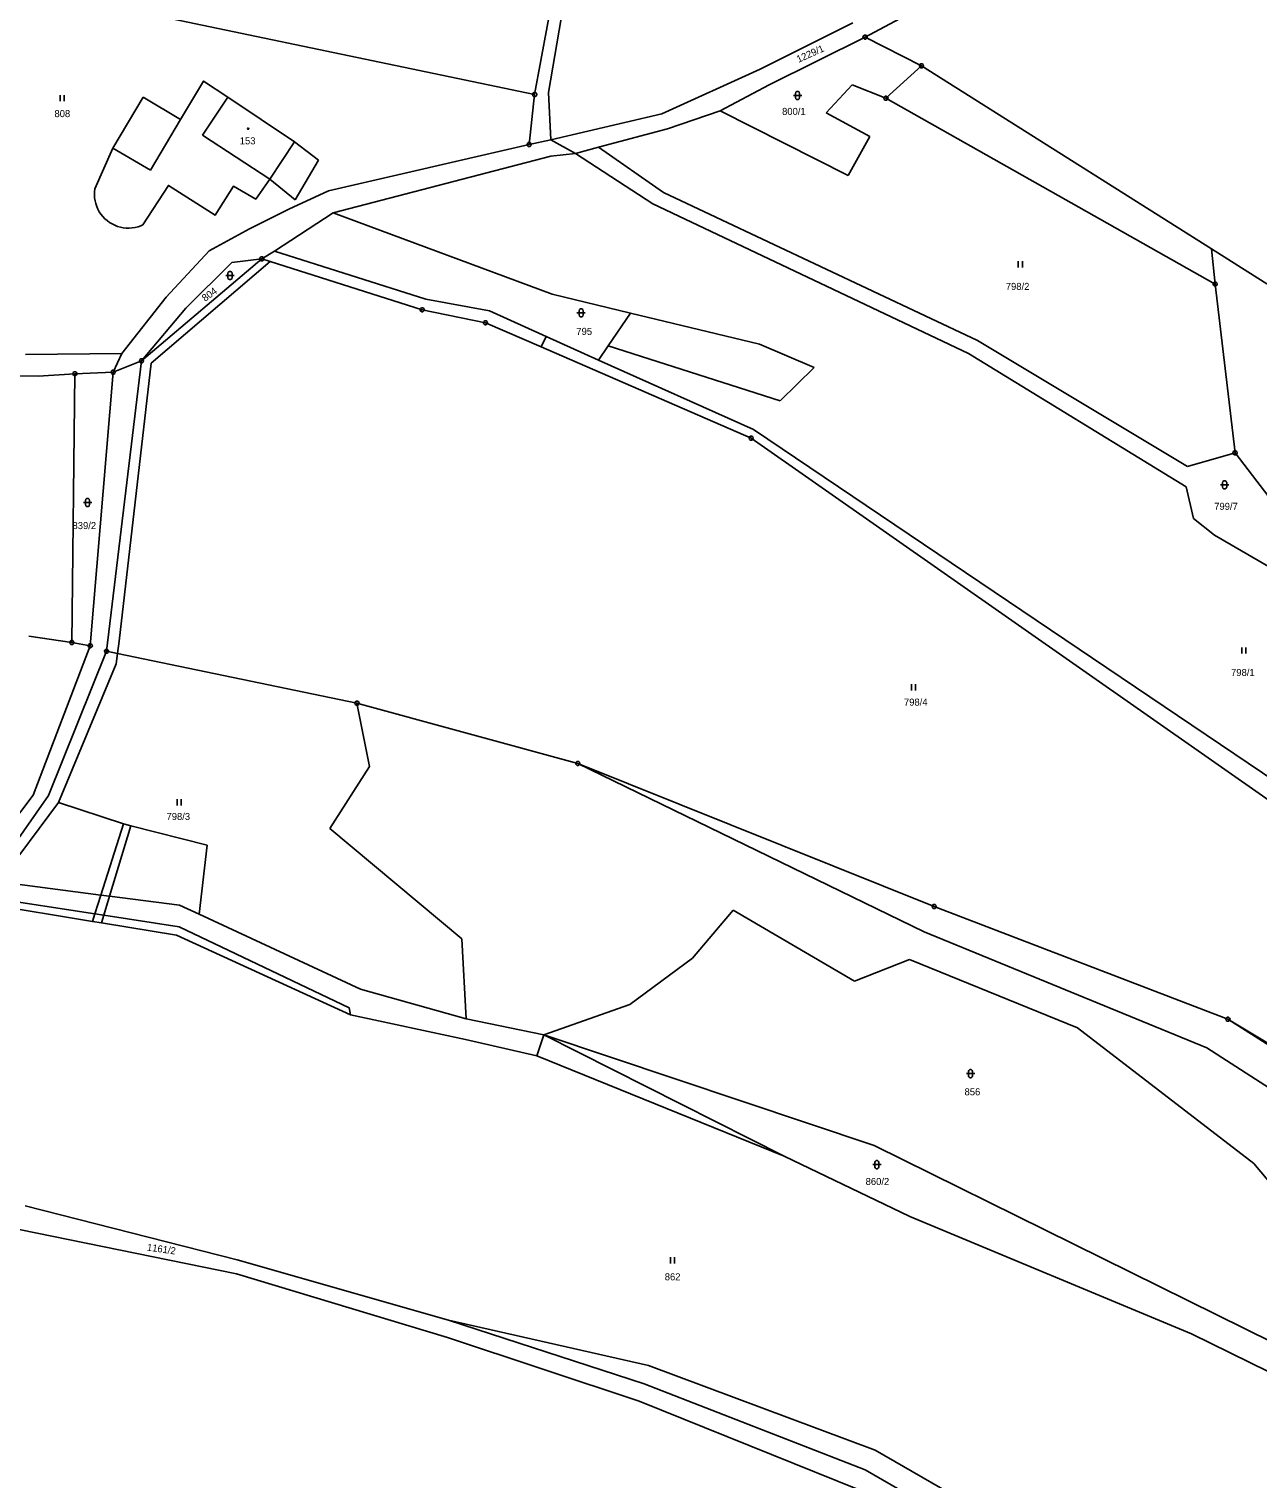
# Model space of a CAD drawing. Extents: x -694465 to -690527, y -983694 to -978978.
# Drawn here: x -691076.6 to -690780.2, y -981049.8 to -980700.1 of the extents above; entities that cross this region are included whole.
import ezdxf

# ---------------------------------------------------------------- set-up
doc = ezdxf.new("R2010")
doc.units = 0
for name, color, linetype in [('Vrstva 1', 7, 'Continuous'), ('Vrstva 18', 7, 'Continuous'), ('Vrstva 19', 7, 'Continuous'), ('Vrstva 24', 7, 'Continuous'), ('Vrstva 25', 7, 'Continuous')]:
    doc.layers.add(name, color=color, linetype=linetype)

msp = doc.modelspace()

# ---------------------------------------------------------------- linework, layer by layer
at = {"layer": 'Vrstva 1'}
for p, q in [((-690944.8, -980730.07), (-690950.76, -980726.8)), ((-690931.555, -980768.6), (-690950.4, -980764.07)), ((-690931.555, -980768.6), (-690936.87, -980776.46)), ((-690931.555, -980768.6), (-690900.39, -980776.09))]:
    msp.add_line(p, q, dxfattribs=at)
for points in [[(-690945.48, -980666.56), (-690954.63, -980715.88)], [(-690951.26, -980715.36), (-690943.69, -980670.66)], [(-690874.96, -980702.01), (-690852.18, -980689.8)], [(-691075.66, -980690.57), (-690954.63, -980715.88)], [(-690877.88, -980698.61), (-690900.24, -980709.79)], [(-690874.96, -980702.01), (-690898.05, -980713.5)], [(-690861.36, -980708.96), (-690874.96, -980702.01)], [(-690900.24, -980709.79), (-690923.97, -980720.55)], [(-690869.93, -980716.78), (-690861.36, -980708.96)], [(-690791.426, -980753.137), (-690861.36, -980708.96)], [(-691040, -980721.87), (-691034.47, -980712.65), (-691028.62, -980716.55)], [(-690898.05, -980713.5), (-690909.88, -980719.84)], [(-690884.37, -980720.29), (-690878.05, -980713.57)], [(-690878.05, -980713.57), (-690869.93, -980716.78)], [(-691056.31, -980728.8), (-691049.06, -980716.52)], [(-691049.06, -980716.52), (-691040, -980721.87)], [(-691034.73, -980725.67), (-691028.62, -980716.55)], [(-691028.62, -980716.55), (-691012.51, -980727.29)], [(-690954.63, -980715.88), (-690955.97, -980727.94)], [(-690950.76, -980726.8), (-690951.26, -980715.36)], [(-690869.93, -980716.78), (-690790.56, -980761.6)], [(-690923.97, -980720.55), (-690950.76, -980726.8)], [(-690922.57, -980724.17), (-690909.88, -980719.84)], [(-690909.88, -980719.84), (-690879.03, -980735.39)], [(-690873.8, -980726.01), (-690884.37, -980720.29)], [(-691040, -980721.87), (-691047.26, -980734.15)], [(-690939.26, -980728.61), (-690922.57, -980724.17)], [(-691018.45, -980736.26), (-691034.73, -980725.67)], [(-691012.51, -980727.29), (-691018.45, -980736.26)], [(-691012.51, -980727.29), (-691006.72, -980731.75)], [(-690955.97, -980727.94), (-691004.33, -980739.14)], [(-690955.97, -980727.94), (-690950.76, -980726.8)], [(-690879.03, -980735.39), (-690873.8, -980726.01)], [(-691018.45, -980736.26), (-691021.87, -980741.09), (-691027.27, -980737.99), (-691031.68, -980744.98), (-691042.95, -980737.81), (-691049.14, -980747.34), (-691049.59, -980747.53), (-691050.27, -980747.77), (-691050.97, -980747.94), (-691051.68, -980748.05), (-691052.39, -980748.1), (-691053.11, -980748.08), (-691053.82, -980748.01), (-691054.52, -980747.87), (-691055.21, -980747.67), (-691055.88, -980747.41), (-691056.52, -980747.09), (-691057.14, -980746.72), (-691057.72, -980746.3), (-691058.26, -980745.83), (-691058.75, -980745.31), (-691059.2, -980744.75), (-691059.6, -980744.16), (-691059.95, -980743.53), (-691060.24, -980742.88), (-691060.47, -980742.2), (-691060.64, -980741.5), (-691060.75, -980740.79), (-691060.8, -980740.08), (-691060.79, -980739.36), (-691060.71, -980738.65), (-691056.31, -980728.8)], [(-691047.26, -980734.15), (-691056.31, -980728.8)], [(-691006.72, -980731.75), (-691012.35, -980741.28)], [(-691003.19, -980744.43), (-690950.72, -980730.72)], [(-690950.72, -980730.72), (-690944.8, -980730.07)], [(-690939.26, -980728.61), (-690944.8, -980730.07)], [(-690944.8, -980730.07), (-690926.14, -980742.28)], [(-690923.55, -980739.51), (-690939.26, -980728.61)], [(-691012.35, -980741.28), (-691018.45, -980736.26)], [(-691004.33, -980739.14), (-691013.9, -980743.51)], [(-690926.14, -980742.28), (-690850.03, -980778.35)], [(-690847.83, -980775.17), (-690923.55, -980739.51)], [(-691013.9, -980743.51), (-691023.4, -980748.27)], [(-691003.19, -980744.43), (-691017.38, -980753.7)], [(-690950.4, -980764.07), (-691003.19, -980744.43)], [(-691023.4, -980748.27), (-691033.14, -980753.6)], [(-691049.45, -980780.12), (-691020.44, -980755.51)], [(-691018.379, -980756.164), (-691047.13, -980780.646)], [(-691033.14, -980753.6), (-691043.51, -980764.76)], [(-691020.44, -980755.51), (-691027.65, -980756.38)], [(-691017.38, -980753.7), (-691020.44, -980755.51)], [(-691020.44, -980755.51), (-691018.379, -980756.164)], [(-691018.379, -980756.164), (-690981.72, -980767.79)], [(-690980.89, -980765.24), (-691017.38, -980753.7)], [(-690764.51, -980770.14), (-690791.426, -980753.137)], [(-690790.56, -980761.6), (-690791.426, -980753.137)], [(-691027.65, -980756.38), (-691038.74, -980767.37)], [(-690790.56, -980761.6), (-690785.76, -980802.28)], [(-691043.51, -980764.76), (-691054.14, -980778.31)], [(-690965.48, -980768.06), (-690980.89, -980765.24)], [(-691038.74, -980767.37), (-691049.45, -980780.12)], [(-690981.72, -980767.79), (-690966.48, -980770.92)], [(-690951.838, -980774.239), (-690965.48, -980768.06)], [(-690966.48, -980770.92), (-690953.088, -980776.742)], [(-690951.838, -980774.239), (-690953.088, -980776.742)], [(-690953.088, -980776.742), (-690902.42, -980798.77)], [(-690939.23, -980779.95), (-690951.838, -980774.239)], [(-690939.23, -980779.95), (-690936.87, -980776.46)], [(-690936.87, -980776.46), (-690895.43, -980789.74)], [(-690887.26, -980781.76), (-690900.39, -980776.09)], [(-690797.24, -980805.59), (-690847.83, -980775.17)], [(-691054.14, -980778.31), (-691077.42, -980778.6)], [(-691057.87, -980850.16), (-691049.45, -980780.12)], [(-691056.28, -980782.84), (-691054.14, -980778.31)], [(-691049.45, -980780.12), (-691056.28, -980782.84)], [(-691047.13, -980780.646), (-691054.784, -980847.69)], [(-690901.83, -980796.7), (-690939.23, -980779.95)], [(-690850.03, -980778.35), (-690797.54, -980810.54)], [(-691105.24, -980783.63), (-691074.36, -980783.83)], [(-691074.36, -980783.83), (-691065.48, -980783.21)], [(-691065.48, -980783.21), (-691066.25, -980848.06)], [(-691065.48, -980783.21), (-691056.28, -980782.84)], [(-691056.28, -980782.84), (-691061.78, -980848.83)], [(-690895.43, -980789.74), (-690887.26, -980781.76)], [(-690775.67, -980881.81), (-690901.83, -980796.7)], [(-690902.42, -980798.77), (-690775.89, -980887.32)], [(-690785.76, -980802.28), (-690797.24, -980805.59)], [(-690764.26, -980830.36), (-690785.76, -980802.28)], [(-690797.54, -980810.54), (-690795.79, -980818.16)], [(-690795.79, -980818.16), (-690790.72, -980822.14)], [(-690790.72, -980822.14), (-690771.18, -980833.48)], [(-691066.25, -980848.06), (-691076.63, -980846.5)], [(-691061.78, -980848.83), (-691075.56, -980884.9)], [(-691071.88, -980884.94), (-691057.87, -980850.16)], [(-691066.25, -980848.06), (-691061.78, -980848.83)], [(-691055.208, -980850.712), (-691057.87, -980850.16)], [(-691055.208, -980850.712), (-691055.557, -980853.196)], [(-691054.784, -980847.69), (-691055.208, -980850.712)], [(-690997.47, -980862.69), (-691055.208, -980850.712)], [(-691055.557, -980853.196), (-691069.466, -980886.636)], [(-690944.22, -980877.22), (-690997.47, -980862.69)], [(-690997.47, -980862.69), (-690994.46, -980878)], [(-690994.46, -980878), (-691003.99, -980892.92)], [(-690858.32, -980911.72), (-690944.22, -980877.22)], [(-690944.22, -980877.22), (-690860.72, -980917.85)], [(-691075.56, -980884.9), (-691090.27, -980904.24)], [(-691086.28, -980905.49), (-691071.88, -980884.94)], [(-691069.466, -980886.636), (-691083.772, -980905.811)], [(-691069.466, -980886.636), (-691053.772, -980891.769)], [(-691053.772, -980891.769), (-691059.211, -980908.956)], [(-691051.963, -980892.235), (-691057.142, -980909.221)], [(-691053.772, -980891.769), (-691051.963, -980892.235)], [(-691051.963, -980892.235), (-691033.627, -980896.958)], [(-691003.99, -980892.92), (-690972.23, -980919.52)], [(-691033.627, -980896.958), (-691035.534, -980913.581)], [(-691059.211, -980908.956), (-691083.772, -980905.811)], [(-691060.648, -980913.494), (-691085.903, -980909.628)], [(-691059.211, -980908.956), (-691060.648, -980913.494)], [(-691057.142, -980909.221), (-691059.211, -980908.956)], [(-691057.142, -980909.221), (-691058.543, -980913.816)], [(-691040.28, -980911.38), (-691057.142, -980909.221)], [(-691086.455, -980911.146), (-691061.223, -980915.312)], [(-691060.648, -980913.494), (-691061.223, -980915.312)], [(-691058.543, -980913.816), (-691060.648, -980913.494)], [(-691035.534, -980913.581), (-691040.28, -980911.38)], [(-690996.61, -980931.63), (-691035.534, -980913.581)], [(-690906.8, -980912.6), (-690916.54, -980924.16)], [(-690877.49, -980929.73), (-690906.8, -980912.6)], [(-690787.46, -980938.93), (-690858.32, -980911.72)], [(-691061.223, -980915.312), (-691059.106, -980915.662)], [(-691058.543, -980913.816), (-691059.106, -980915.662)], [(-691059.106, -980915.662), (-691041.01, -980918.65)], [(-691040.353, -980916.601), (-691058.543, -980913.816)], [(-691040.353, -980916.601), (-690999.318, -980936.185), (-690999, -980937.84)], [(-691041.01, -980918.65), (-690999, -980937.84)], [(-690972.23, -980919.52), (-690971.18, -980938.81)], [(-690860.72, -980917.85), (-690792.58, -980945.83)], [(-690916.54, -980924.16), (-690931.71, -980935.34)], [(-690864.23, -980924.53), (-690877.49, -980929.73)], [(-690823.72, -980940.99), (-690864.23, -980924.53)], [(-690971.18, -980938.81), (-690996.61, -980931.63)], [(-690999, -980937.84), (-690971.32, -980943.84)], [(-690931.71, -980935.34), (-690952.43, -980942.7)], [(-690952.43, -980942.7), (-690971.18, -980938.81)], [(-690781.23, -980973.71), (-690823.72, -980940.99)], [(-690643.63, -981025.36), (-690787.46, -980938.93)], [(-690636.2, -981034.92), (-690787.46, -980938.93)], [(-690971.32, -980943.84), (-690954.09, -980947.72)], [(-690954.09, -980947.72), (-690952.43, -980942.7)], [(-690952.43, -980942.7), (-690894.47, -980971.92)], [(-690872.79, -980969.37), (-690952.43, -980942.7)], [(-690894.47, -980971.92), (-690954.09, -980947.72)], [(-690792.58, -980945.83), (-690743.36, -980977.51)], [(-690776.49, -981016.99), (-690872.79, -980969.37)], [(-690894.47, -980971.92), (-690864.17, -980986.51)], [(-690758.75, -981000.52), (-690781.23, -980973.71)], [(-691026.38, -980996.99), (-691077.45, -980983.96)], [(-690864.17, -980986.51), (-690796.27, -981014.8)], [(-691078.96, -980989.62), (-691026.49, -981000.36)], [(-690975.39, -981011.49), (-691026.38, -980996.99)], [(-691026.49, -981000.36), (-690975.65, -981015.66)], [(-690927.18, -981022.44), (-690975.39, -981011.49)], [(-690975.39, -981011.49), (-690928.23, -981026.86)], [(-690796.27, -981014.8), (-690731.16, -981046.82)], [(-690975.65, -981015.66), (-690929.44, -981031.04)], [(-690872.49, -981042.88), (-690927.18, -981022.44)], [(-690928.23, -981026.86), (-690874.9, -981047.64)], [(-690929.44, -981031.04), (-690876.42, -981052.46)], [(-690787.89, -981091.69), (-690872.49, -981042.88)], [(-690874.9, -981047.64), (-690791.5, -981095.75)]]:
    msp.add_lwpolyline(points, dxfattribs=at)
at = {"layer": 'Vrstva 24'}
for points in [[(-690874.806, -980701.534), (-690874.556, -980701.716), (-690874.46, -980702.01), (-690874.556, -980702.304), (-690874.806, -980702.486), (-690875.114, -980702.486), (-690875.364, -980702.304), (-690875.46, -980702.01), (-690875.364, -980701.716), (-690875.114, -980701.534)], [(-690861.206, -980708.484), (-690860.956, -980708.666), (-690860.86, -980708.96), (-690860.956, -980709.254), (-690861.206, -980709.436), (-690861.514, -980709.436), (-690861.764, -980709.254), (-690861.86, -980708.96), (-690861.764, -980708.666), (-690861.514, -980708.484)], [(-690954.476, -980715.404), (-690954.226, -980715.586), (-690954.13, -980715.88), (-690954.226, -980716.174), (-690954.476, -980716.356), (-690954.784, -980716.356), (-690955.034, -980716.174), (-690955.13, -980715.88), (-690955.034, -980715.586), (-690954.784, -980715.404)], [(-690869.776, -980716.304), (-690869.526, -980716.486), (-690869.43, -980716.78), (-690869.526, -980717.074), (-690869.776, -980717.256), (-690870.084, -980717.256), (-690870.334, -980717.074), (-690870.43, -980716.78), (-690870.334, -980716.486), (-690870.084, -980716.304)], [(-690955.816, -980727.464), (-690955.566, -980727.646), (-690955.47, -980727.94), (-690955.566, -980728.234), (-690955.816, -980728.416), (-690956.124, -980728.416), (-690956.374, -980728.234), (-690956.47, -980727.94), (-690956.374, -980727.646), (-690956.124, -980727.464)], [(-691020.286, -980755.034), (-691020.036, -980755.216), (-691019.94, -980755.51), (-691020.036, -980755.804), (-691020.286, -980755.986), (-691020.594, -980755.986), (-691020.844, -980755.804), (-691020.94, -980755.51), (-691020.844, -980755.216), (-691020.594, -980755.034)], [(-690790.406, -980761.124), (-690790.156, -980761.306), (-690790.06, -980761.6), (-690790.156, -980761.894), (-690790.406, -980762.076), (-690790.714, -980762.076), (-690790.964, -980761.894), (-690791.06, -980761.6), (-690790.964, -980761.306), (-690790.714, -980761.124)], [(-690981.566, -980767.314), (-690981.316, -980767.496), (-690981.22, -980767.79), (-690981.316, -980768.084), (-690981.566, -980768.266), (-690981.874, -980768.266), (-690982.124, -980768.084), (-690982.22, -980767.79), (-690982.124, -980767.496), (-690981.874, -980767.314)], [(-690966.326, -980770.444), (-690966.076, -980770.626), (-690965.98, -980770.92), (-690966.076, -980771.214), (-690966.326, -980771.396), (-690966.634, -980771.396), (-690966.884, -980771.214), (-690966.98, -980770.92), (-690966.884, -980770.626), (-690966.634, -980770.444)], [(-691049.296, -980779.644), (-691049.046, -980779.826), (-691048.95, -980780.12), (-691049.046, -980780.414), (-691049.296, -980780.596), (-691049.604, -980780.596), (-691049.854, -980780.414), (-691049.95, -980780.12), (-691049.854, -980779.826), (-691049.604, -980779.644)], [(-691065.326, -980782.734), (-691065.076, -980782.916), (-691064.98, -980783.21), (-691065.076, -980783.504), (-691065.326, -980783.686), (-691065.634, -980783.686), (-691065.884, -980783.504), (-691065.98, -980783.21), (-691065.884, -980782.916), (-691065.634, -980782.734)], [(-691056.126, -980782.364), (-691055.876, -980782.546), (-691055.78, -980782.84), (-691055.876, -980783.134), (-691056.126, -980783.316), (-691056.434, -980783.316), (-691056.684, -980783.134), (-691056.78, -980782.84), (-691056.684, -980782.546), (-691056.434, -980782.364)], [(-690902.266, -980798.294), (-690902.016, -980798.476), (-690901.92, -980798.77), (-690902.016, -980799.064), (-690902.266, -980799.246), (-690902.574, -980799.246), (-690902.824, -980799.064), (-690902.92, -980798.77), (-690902.824, -980798.476), (-690902.574, -980798.294)], [(-690785.606, -980801.804), (-690785.356, -980801.986), (-690785.26, -980802.28), (-690785.356, -980802.574), (-690785.606, -980802.756), (-690785.914, -980802.756), (-690786.164, -980802.574), (-690786.26, -980802.28), (-690786.164, -980801.986), (-690785.914, -980801.804)], [(-691066.096, -980847.584), (-691065.846, -980847.766), (-691065.75, -980848.06), (-691065.846, -980848.354), (-691066.096, -980848.536), (-691066.404, -980848.536), (-691066.654, -980848.354), (-691066.75, -980848.06), (-691066.654, -980847.766), (-691066.404, -980847.584)], [(-691061.626, -980848.354), (-691061.376, -980848.536), (-691061.28, -980848.83), (-691061.376, -980849.124), (-691061.626, -980849.306), (-691061.934, -980849.306), (-691062.184, -980849.124), (-691062.28, -980848.83), (-691062.184, -980848.536), (-691061.934, -980848.354)], [(-691057.716, -980849.684), (-691057.466, -980849.866), (-691057.37, -980850.16), (-691057.466, -980850.454), (-691057.716, -980850.636), (-691058.024, -980850.636), (-691058.274, -980850.454), (-691058.37, -980850.16), (-691058.274, -980849.866), (-691058.024, -980849.684)], [(-690997.316, -980862.214), (-690997.066, -980862.396), (-690996.97, -980862.69), (-690997.066, -980862.984), (-690997.316, -980863.166), (-690997.624, -980863.166), (-690997.874, -980862.984), (-690997.97, -980862.69), (-690997.874, -980862.396), (-690997.624, -980862.214)], [(-690944.066, -980876.744), (-690943.816, -980876.926), (-690943.72, -980877.22), (-690943.816, -980877.514), (-690944.066, -980877.696), (-690944.374, -980877.696), (-690944.624, -980877.514), (-690944.72, -980877.22), (-690944.624, -980876.926), (-690944.374, -980876.744)], [(-690858.166, -980911.244), (-690857.916, -980911.426), (-690857.82, -980911.72), (-690857.916, -980912.014), (-690858.166, -980912.196), (-690858.474, -980912.196), (-690858.724, -980912.014), (-690858.82, -980911.72), (-690858.724, -980911.426), (-690858.474, -980911.244)], [(-690787.306, -980938.454), (-690787.056, -980938.636), (-690786.96, -980938.93), (-690787.056, -980939.224), (-690787.306, -980939.406), (-690787.614, -980939.406), (-690787.864, -980939.224), (-690787.96, -980938.93), (-690787.864, -980938.636), (-690787.614, -980938.454)]]:
    msp.add_lwpolyline(points, close=True, dxfattribs=at)
for points in [[(-690875.079, -980702.01), (-690874.84, -980702.01)], [(-690861.479, -980708.96), (-690861.24, -980708.96)], [(-690954.749, -980715.88), (-690954.51, -980715.88)], [(-690870.049, -980716.78), (-690869.81, -980716.78)], [(-690956.089, -980727.94), (-690955.85, -980727.94)], [(-691020.559, -980755.51), (-691020.32, -980755.51)], [(-690790.679, -980761.6), (-690790.44, -980761.6)], [(-690981.839, -980767.79), (-690981.6, -980767.79)], [(-690966.599, -980770.92), (-690966.36, -980770.92)], [(-691049.569, -980780.12), (-691049.33, -980780.12)], [(-691065.599, -980783.21), (-691065.36, -980783.21)], [(-691056.399, -980782.84), (-691056.16, -980782.84)], [(-690902.539, -980798.77), (-690902.3, -980798.77)], [(-690785.879, -980802.28), (-690785.64, -980802.28)], [(-691066.369, -980848.06), (-691066.13, -980848.06)], [(-691061.899, -980848.83), (-691061.66, -980848.83)], [(-691057.989, -980850.16), (-691057.75, -980850.16)], [(-690997.589, -980862.69), (-690997.35, -980862.69)], [(-690944.339, -980877.22), (-690944.1, -980877.22)], [(-690858.439, -980911.72), (-690858.2, -980911.72)], [(-690787.579, -980938.93), (-690787.34, -980938.93)]]:
    msp.add_lwpolyline(points, dxfattribs=at)
at = {"layer": 'Vrstva 25'}
for points in [[(-691069.04, -980716), (-691069.04, -980717.5)], [(-691068.04, -980717.5), (-691068.04, -980716)], [(-690892.24, -980716.1), (-690890.24, -980716.1)], [(-690838.03, -980756.11), (-690838.03, -980757.61)], [(-690837.03, -980757.61), (-690837.03, -980756.11)], [(-691029.09, -980759.55), (-691027.09, -980759.55)], [(-690944.43, -980768.54), (-690942.43, -980768.54)], [(-690789.27, -980810.03), (-690787.27, -980810.03)], [(-691063.44, -980814.3), (-691061.44, -980814.3)], [(-690784.14, -980849.23), (-690784.14, -980850.73)], [(-690783.14, -980850.73), (-690783.14, -980849.23)], [(-690863.79, -980858.11), (-690863.79, -980859.61)], [(-690862.79, -980859.61), (-690862.79, -980858.11)], [(-691040.85, -980885.86), (-691040.85, -980887.36)], [(-691039.85, -980887.36), (-691039.85, -980885.86)], [(-690850.52, -980952.05), (-690848.52, -980952.05)], [(-690873.11, -980974), (-690871.11, -980974)], [(-690921.91, -980996.34), (-690921.91, -980997.84)], [(-690920.91, -980997.84), (-690920.91, -980996.34)]]:
    msp.add_lwpolyline(points, dxfattribs=at)
for points in [[(-690891.74, -980715.6), (-690891.645, -980715.306), (-690891.395, -980715.124), (-690891.085, -980715.124), (-690890.835, -980715.306), (-690890.74, -980715.6), (-690890.74, -980716.6), (-690890.835, -980716.894), (-690891.085, -980717.076), (-690891.395, -980717.076), (-690891.645, -980716.894), (-690891.74, -980716.6)], [(-691023.623, -980723.968), (-691023.535, -980724.12), (-691023.623, -980724.272), (-691023.797, -980724.272), (-691023.885, -980724.12), (-691023.797, -980723.968)], [(-691028.59, -980759.05), (-691028.495, -980758.756), (-691028.245, -980758.574), (-691027.935, -980758.574), (-691027.685, -980758.756), (-691027.59, -980759.05), (-691027.59, -980760.05), (-691027.685, -980760.344), (-691027.935, -980760.526), (-691028.245, -980760.526), (-691028.495, -980760.344), (-691028.59, -980760.05)], [(-690943.93, -980768.04), (-690943.835, -980767.746), (-690943.585, -980767.564), (-690943.275, -980767.564), (-690943.025, -980767.746), (-690942.93, -980768.04), (-690942.93, -980769.04), (-690943.025, -980769.334), (-690943.275, -980769.516), (-690943.585, -980769.516), (-690943.835, -980769.334), (-690943.93, -980769.04)], [(-690788.77, -980809.53), (-690788.675, -980809.236), (-690788.425, -980809.054), (-690788.115, -980809.054), (-690787.865, -980809.236), (-690787.77, -980809.53), (-690787.77, -980810.53), (-690787.865, -980810.824), (-690788.115, -980811.006), (-690788.425, -980811.006), (-690788.675, -980810.824), (-690788.77, -980810.53)], [(-691062.94, -980813.8), (-691062.845, -980813.506), (-691062.595, -980813.324), (-691062.285, -980813.324), (-691062.035, -980813.506), (-691061.94, -980813.8), (-691061.94, -980814.8), (-691062.035, -980815.094), (-691062.285, -980815.276), (-691062.595, -980815.276), (-691062.845, -980815.094), (-691062.94, -980814.8)], [(-690850.02, -980951.55), (-690849.925, -980951.256), (-690849.675, -980951.074), (-690849.365, -980951.074), (-690849.115, -980951.256), (-690849.02, -980951.55), (-690849.02, -980952.55), (-690849.115, -980952.844), (-690849.365, -980953.026), (-690849.675, -980953.026), (-690849.925, -980952.844), (-690850.02, -980952.55)], [(-690872.61, -980973.5), (-690872.515, -980973.206), (-690872.265, -980973.024), (-690871.955, -980973.024), (-690871.705, -980973.206), (-690871.61, -980973.5), (-690871.61, -980974.5), (-690871.705, -980974.794), (-690871.955, -980974.976), (-690872.265, -980974.976), (-690872.515, -980974.794), (-690872.61, -980974.5)]]:
    msp.add_lwpolyline(points, close=True, dxfattribs=at)

# ---------------------------------------------------------------- texts
at = {"layer": 'Vrstva 18'}
for s, rotation, p in [('1229/1', 24.29341, (-690891.007, -980708.24)), ('804', 35.98175, (-691034.085, -980765.88)), ('1161/2', 351.91068, (-691048.191, -980994.705))]:
    msp.add_text(s, height=1.7, rotation=rotation, dxfattribs=at).set_placement(p)
for s, p in [('808', (-691070.418, -980721.33)), ('800/1', (-690894.975, -980720.8)), ('798/2', (-690841.023, -980763.01)), ('795', (-690944.581, -980773.86)), ('799/7', (-690790.773, -980816.06)), ('839/2', (-691066.061, -980820.7)), ('798/1', (-690786.712, -980856.13)), ('798/4', (-690865.583, -980863.28)), ('798/3', (-691043.397, -980890.86)), ('856', (-690850.973, -980957.28)), ('860/2', (-690874.823, -980978.9)), ('862', (-690923.265, -981001.9))]:
    msp.add_text(s, height=1.7, dxfattribs=at).set_placement(p)
at = {"layer": 'Vrstva 19'}
msp.add_text('153', height=1.7, dxfattribs=at).set_placement((-691025.74, -980727.89))

doc.saveas('drawing.dxf')
